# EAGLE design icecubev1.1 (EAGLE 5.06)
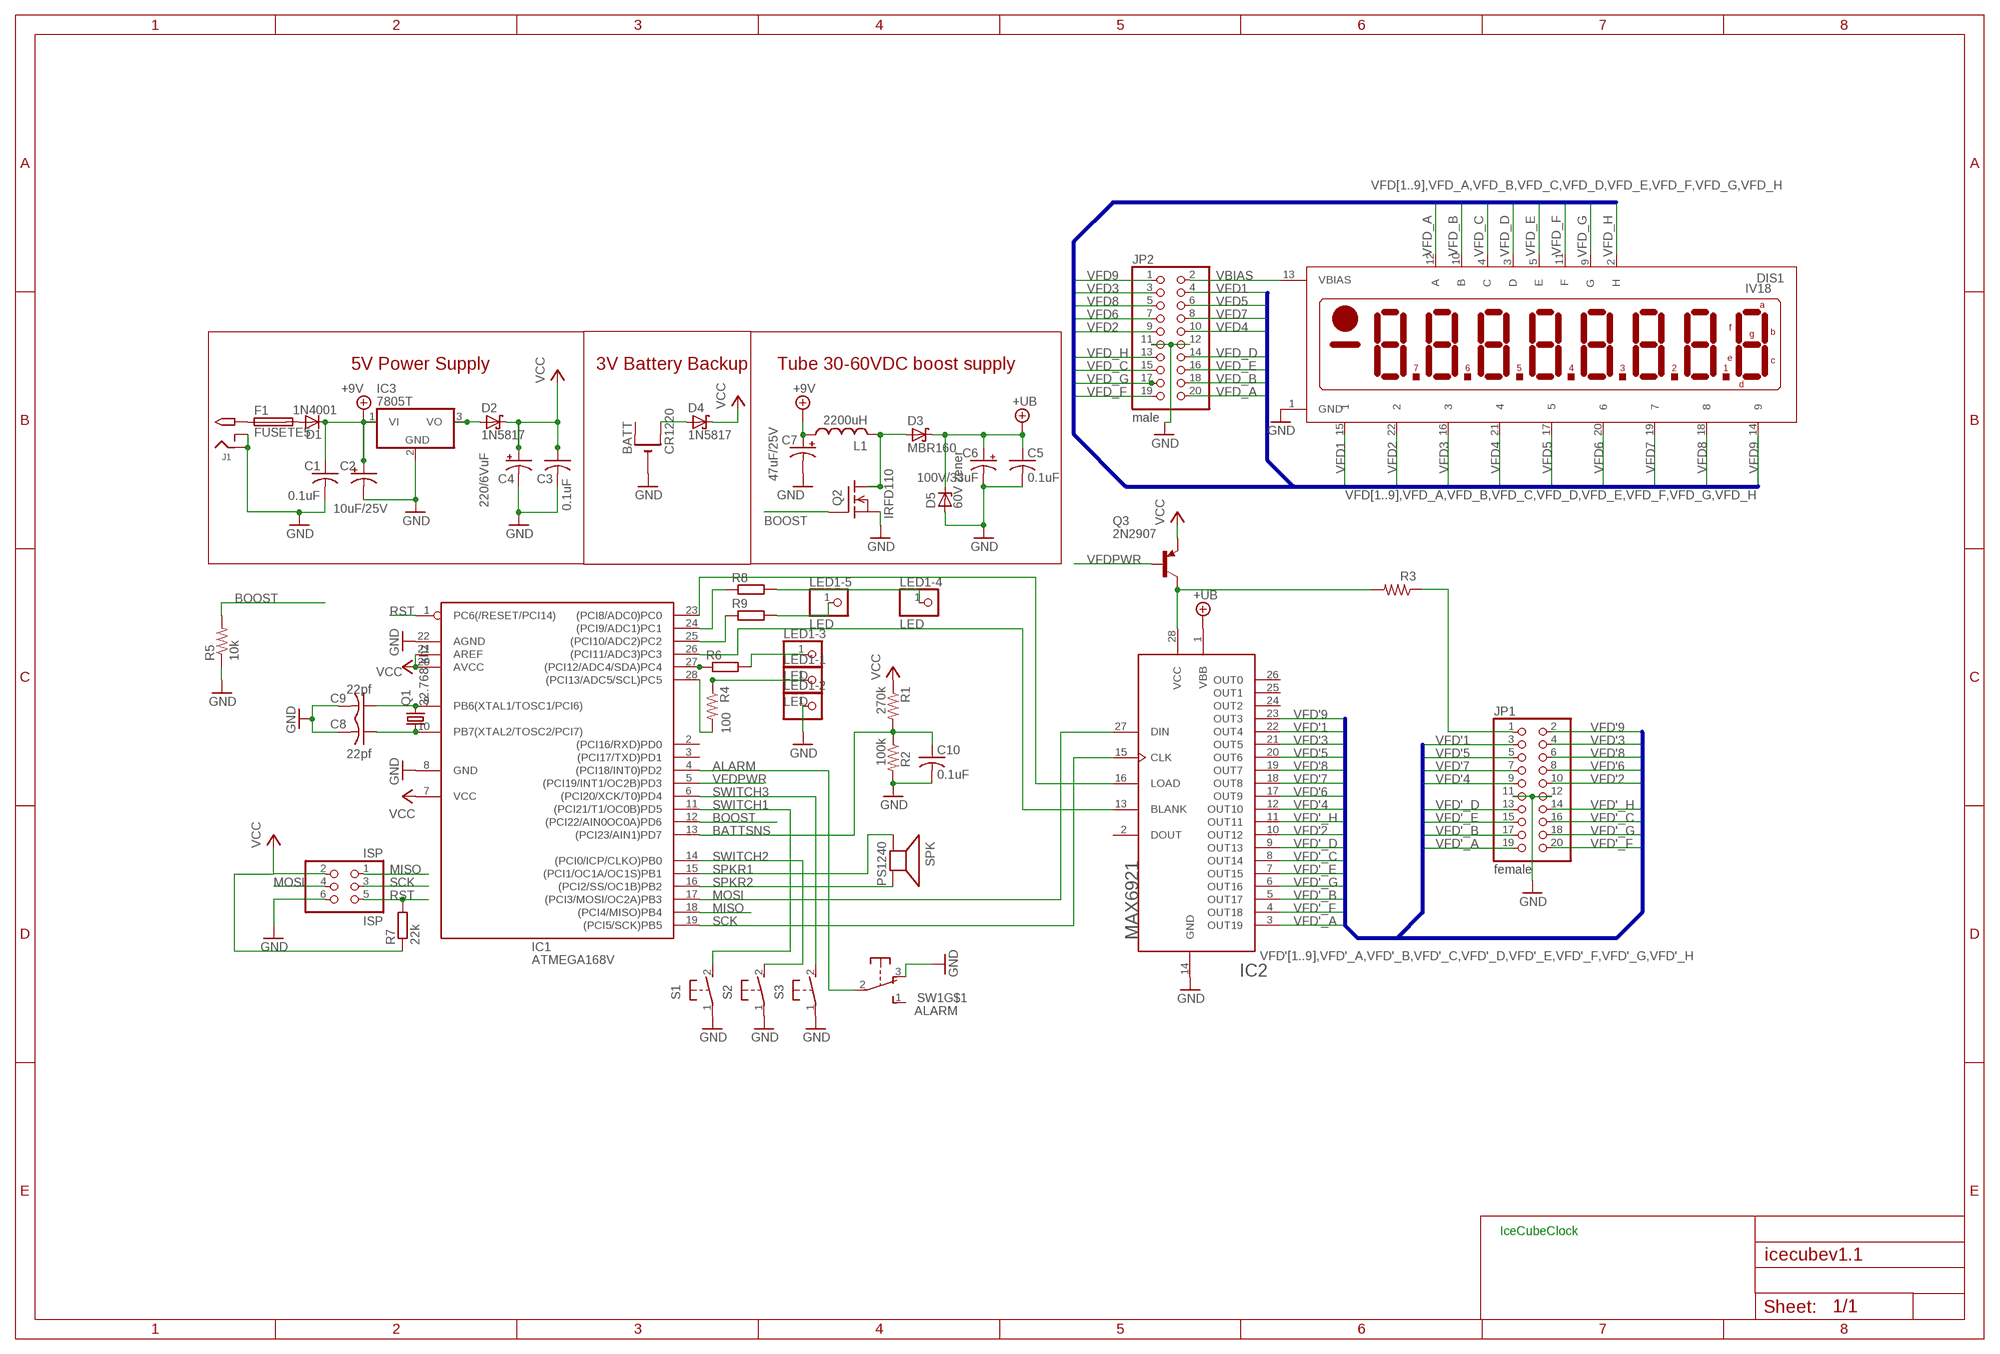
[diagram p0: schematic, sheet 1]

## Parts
BATT  CR1220  CR1220THM  [CR1220-THM]
C1  0.1uF  C-US025-025X050  [C025-025X050]
C2  10uF/25V  CPOL-USE2.5-6  [E2,5-6]
C3  0.1uF  C-US025-025X050  [C025-025X050]
C4  220/6VuF  CPOL-USE2.5-6  [E2,5-6]
C5  0.1uF  C-US025-024X044  [C025-024X044]
C6  100V/33uF  CPOL-USE3.5-8  [E3,5-8]
C7  47uF/25V  CPOL-USE2.5-6  [E2,5-6]
C8  22pf  C-US025-025X050  [C025-025X050]
C9  22pf  C-US025-025X050  [C025-025X050]
C10  0.1uF  C-US025-024X044  [C025-024X044]
D1  1N4001  1N4004  [DO41-10]
D2  1N5817  SCHOTTKY-DIODEDO41  [DO41-10]
D3  MBR160  SCHOTTKY-DIODEDO41  [DO41-10]
D4  1N5817  SCHOTTKY-DIODEDO41  [DO41-10]
D5  60V zener  ZENER-DIODEDO41Z10  [DO41Z10]
DIS1  IV18  [IV18]
F1  FUSETE5  [TE5]
IC1  ATMEGA168V  ATMEGA168PROUND  [DIL28/3]
IC2  MAX6921  [PLCC-S28]
IC3  7805T  [TO220H]
ISP  ISP  PINHD-2X3  [2X03]
J1  2.1MMJACK  [PJ-102A]
JP1  female  PINHD-2X10  [2X10]
JP2  male  PINHD-2X10  [2X10]
L1  2200uH  L  [6000]
LED1-1  LED  PINHD-1X1  [1X01]
LED1-2  PINHD-1X1  [1X01]
LED1-3  LED  PINHD-1X1  [1X01]
LED1-4  LED  PINHD-1X1  [1X01]
LED1-5  LED  PINHD-1X1  [1X01]
Q1  32.768 khz  CRYTALTC26V  [TC26V]
Q2  IRFD110  [DIL04]
Q3  2N2907  BC327-16-PNP-TO92-EBC  [TO92-EBC]
R1  270k  R-US_0207/10  [0207/10]
R2  100k  R-US_0207/10  [0207/10]
R3  22  R-US_0207/10  [0207/10]
R4  100  R-US_0207/5V  [0207/5V]
R5  10k  R-US_0207/5V  [0207/5V]
R6  R-EU_0204/5  [0204/5]
R7  22k  R-EU_0204/2V  [0204V]
R8  R-EU_0204/5  [0204/5]
R9  R-EU_0204/5  [0204/5]
S1  31-XX  [B3F-31XX]
S2  31-XX  [B3F-31XX]
S3  31-XX  [B3F-31XX]
SPK  PS1240  SPEAKER/PS12  [PS12]
SW1  ALARM  OS102011MA1Q  [OS102011MA1Q]

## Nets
+9V: C1.1 C2.+ C7.+ D1.C IC3.1(VI) L1.1
+UB: C5.1 C6.+ D3.C D5.C IC2.1(VBB)
ALARM: IC1.4((PCI18/INT0)PD2) SW1.2(P)
BATTSNS: C10.1 IC1.13((PCI23/AIN1)PD7) R1.2 R2.1
BLANK: IC1.26((PCI11/ADC3)PC3) IC2.13(BLANK)
BOOST: IC1.12((PCI22/AIN0OC0A)PD6) Q2.3(G) R5.2
GND: BATT.- C1.2 C2.- C3.2 C4.- C5.2 C6.- C7.- C8.2 C9.2 C10.2 D5.A DIS1.1(GND) IC1.8(GND) IC1.22(AGND) IC2.14(GND) IC3.2(GND) ISP.6 J1.RING J1.RING_SW JP1.11 JP1.12 JP2.11 JP2.12 LED1-2.1 Q2.4(S) R2.2 R5.1 S1.1(P) S2.1(P) S3.1(P) SW1.3(O)
LOAD: IC1.23((PCI8/ADC0)PC0) IC2.16(LOAD)
MISO: IC1.18((PCI4/MISO)PB4) ISP.1
MOSI: IC1.17((PCI3/MOSI/OC2A)PB3) IC2.27(DIN) ISP.4
N$1: C9.1 IC1.9(PB6(XTAL1/TOSC1/PCI6)) Q1.2
N$2: D3.A L1.2 Q2.1(D) Q2.2(D1)
N$3: C8.1 IC1.10(PB7(XTAL2/TOSC2/PCI7)) Q1.1
N$4: F1.1 J1.TIP
N$5: D1.A F1.2
N$6: IC1.27((PCI12/ADC4/SDA)PC4) R6.1
N$7: LED1-3.1 R6.2
N$8: IC1.24((PCI9/ADC1)PC1) R8.1
N$9: IC1.25((PCI10/ADC2)PC2) R9.1
N$10: BATT.+2(+1) D4.A
N$11: IC1.28((PCI13/ADC5/SCL)PC5) R4.2
N$12: LED1-5.1 R9.2
N$13: LED1-4.1 R8.2
N$34: JP1.1 R3.1
N$39: IC2.28(VCC) Q3.C R3.2
N$52: LED1-1.1 R4.1
N$53: D2.A IC3.3(VO)
RST: IC1.1(PC6(/RESET/PCI14)) ISP.5 R7.2
SCK: IC1.19((PCI5/SCK)PB5) IC2.15(CLK) ISP.3
SPKR1: IC1.15((PCI1/OC1A/OC1S)PB1) SPK.P$1(+)
SPKR2: IC1.16((PCI2/SS/OC1B)PB2) SPK.P$2(-)
SWITCH1: IC1.11((PCI21/T1/OC0B)PD5) S1.2(S)
SWITCH2: IC1.14((PCI0/ICP/CLKO)PB0) S2.2(S)
SWITCH3: IC1.6((PCI20/XCK/T0)PD4) S3.2(S)
VBIAS: DIS1.13(VBIAS) JP2.2
VCC: C3.1 C4.+ D2.C D4.C IC1.7(VCC) IC1.20(AVCC) IC1.21(AREF) ISP.2 Q3.E R1.1 R7.1
VFD1: DIS1.15 JP2.4
VFD2: DIS1.22 JP2.9
VFD3: DIS1.16 JP2.3
VFD4: DIS1.21 JP2.10
VFD5: DIS1.17 JP2.6
VFD6: DIS1.20 JP2.7
VFD7: DIS1.19 JP2.8
VFD8: DIS1.18 JP2.5
VFD9: DIS1.14 JP2.1
VFD'1: IC2.22(OUT4) JP1.3
VFD'2: IC2.10(OUT12) JP1.10
VFD'3: IC2.21(OUT5) JP1.4
VFD'4: IC2.12(OUT10) JP1.9
VFD'5: IC2.20(OUT6) JP1.5
VFD'6: IC2.17(OUT9) JP1.8
VFD'7: IC2.18(OUT8) JP1.7
VFD'8: IC2.19(OUT7) JP1.6
VFD'9: IC2.23(OUT3) JP1.2
VFD'_A: IC2.3(OUT19) JP1.19
VFD'_B: IC2.5(OUT17) JP1.17
VFD'_C: IC2.8(OUT14) JP1.16
VFD'_D: IC2.9(OUT13) JP1.13
VFD'_E: IC2.7(OUT15) JP1.15
VFD'_F: IC2.4(OUT18) JP1.20
VFD'_G: IC2.6(OUT16) JP1.18
VFD'_H: IC2.11(OUT11) JP1.14
VFD_A: DIS1.12(A) JP2.20
VFD_B: DIS1.10(B) JP2.18
VFD_C: DIS1.4(C) JP2.15
VFD_D: DIS1.3(D) JP2.14
VFD_E: DIS1.5(E) JP2.16
VFD_F: DIS1.11(F) JP2.19
VFD_G: DIS1.9(G) JP2.17
VFD_H: DIS1.2(H) JP2.13
VFDPWR: IC1.5((PCI19/INT1/OC2B)PD3) Q3.B
Unconnected: BATT.+1(+) IC1.2((PCI16/RXD)PD0) IC1.3((PCI17/TXD)PD1) IC2.2(DOUT) IC2.24(OUT2) IC2.25(OUT1) IC2.26(OUT0) SW1.1(S) SW1.MT1(MT) SW1.MT2(MT)

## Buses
VFD[1..9],VFD_A,VFD_B,VFD_C,VFD_D,VFD_E,VFD_F,VFD_G,VFD_H
VFD'[1..9],VFD'_A,VFD'_B,VFD'_C,VFD'_D,VFD'_E,VFD'_F,VFD'_G,VFD'_H

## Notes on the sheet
- 5V Power Supply | 3V Battery Backup | Tube 30-60VDC boost supply
- IceCubeClock

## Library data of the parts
BATT = vfd:CR1220
C1 C3 C8 C9 = minimidi:C-US: CAPACITOR, American symbol
C2 C4 C7 = minimidi:CPOL-US: POLARIZED CAPACITOR, American symbol
C5 C10 = rcl-ez:C-US: CAPACITOR, American symbol
C6 = rcl-ez:CPOL-US: POLARIZED CAPACITOR, American symbol
D1 = minimidi:1N4004: DIODE
D2-D4 = usbbuck:SCHOTTKY-DIODE: Schottky Diode
D5 = diode:ZENER-DIODE: Z-Diode
DIS1 = vfd:IV18: LCD DISPLAY 8-character 7 segment
F1 = fuse:FUSE: Fuse
IC1 = avr:ATMEGA168*P: MICROCONTROLLER 16 kBytes FLASH 1 kBytes SRAM 512 Bytes EEPROM USART 8-channel 10 bit ADC
IC2 = vfd:MAX6921
IC3 = linear:78*: Positive VOLTAGE REGULATOR
ISP = pinhead-ez:PINHD-2X3: PIN HEADER
J1 = minimidi:2.1MMJACK
JP1 JP2 = pinhead:PINHD-2X10: PIN HEADER
L1 = usbbuck:L
LED1-1-LED1-5 = ybox2:PINHD-1X1: PIN HEADER
Q1 = crystal:CRYTAL: CRYSTAL
Q2 = vfd:IRFD110
Q3 = transistor:*-PNP-: PNP Transistror
R1-R5 = minimidi:R-US_: RESISTOR, American symbol
R6 R8 R9 = resistor:R-EU_: RESISTOR, European symbol
R7 = rcl:R-EU_: RESISTOR, European symbol
S1-S3 = switch-omron:31-XX: OMRON SWITCH
SPK = ybox2:SPEAKER: SPEAKER
SW1 = adaprog:OS102011MA1Q

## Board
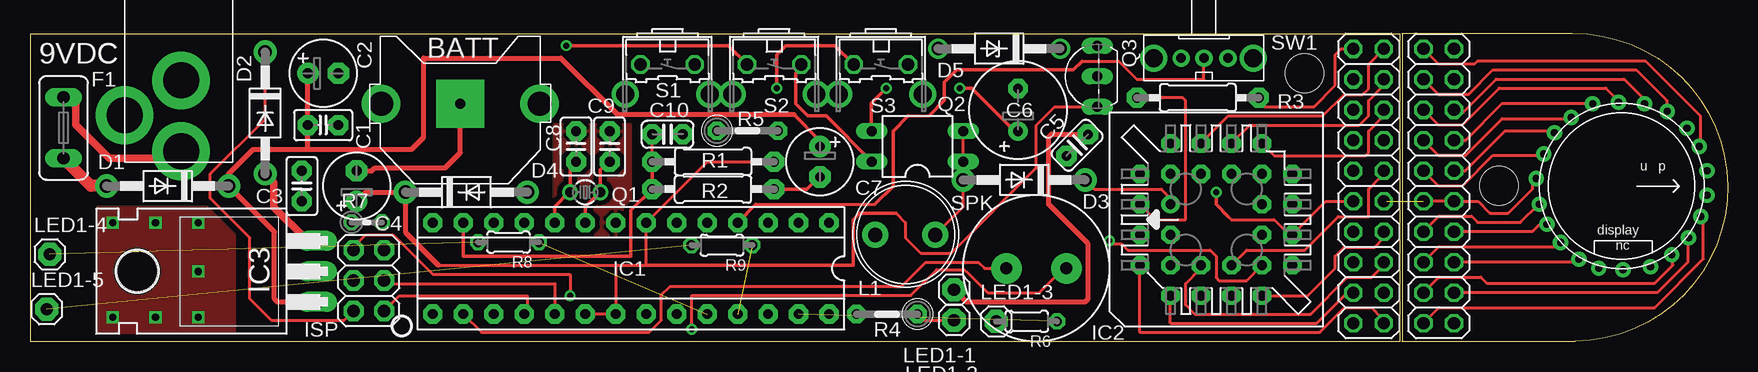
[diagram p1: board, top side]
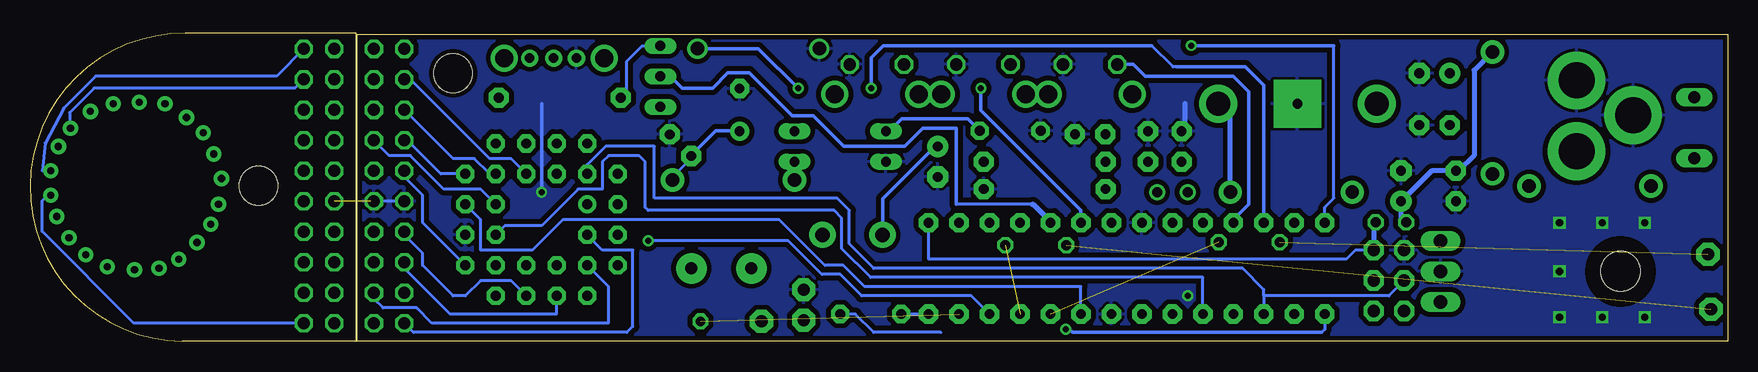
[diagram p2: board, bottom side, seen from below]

Size 141.47 x 25.68 mm. Coordinates in mm from the lower left corner, seen from the top.
Outline: 114.34,25.65 114.34,0
Outline: 114.3,0.03 128.77,0.03 arc180 128.52,25.68 114.3,25.68
Outline: 0,0.04 114.2,0.04 114.2,25.62 0,25.62 0,0.04
Copper layers (1*16): Top 0.035mm / dielectric 1.5mm / Bottom 0.035mm
Design rules "default *": minimum track width 10mil, minimum drill 19mil, track to track 12mil, track to pad 12mil, pad to pad 20mil, via to via 12mil, smd to smd 0mil, copper to edge 12mil, drill to drill 8mil, minimum pad ring 10mil, minimum via ring 8mil, stop-mask expansion 4mil, vias tented up to drill 20mil, thermal gap 10mil
Holes 3.2 mm at 106.21,22.35 122.42,12.98

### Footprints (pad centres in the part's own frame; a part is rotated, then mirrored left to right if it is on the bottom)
CR1220-THM = drill 2 pad 3.175 round: +1 -6.604,0; +2 6.604,0 | drill 0.8 pad 3.962 square: - 0,0
C025-025X050 = drill 0.813 pad 1.676 octagon: 1 -1.27,0; 2 1.27,0
E2,5-6 = drill 0.813 pad 1.778 round: + -1.27,0 | drill 0.813 pad 1.778 octagon: - 1.27,0
C025-024X044 = drill 0.813 pad 1.676 octagon: 1 -1.27,0; 2 1.27,0
E3,5-8 = drill 0.813 pad 1.6 round: + -1.778,0 | drill 0.813 pad 1.6 octagon: - 1.778,0
DO41-10 = drill 1.118 pad 1.93 round: A 5.08,0; C -5.08,0
DO41Z10 = drill 1.118 round: A 5.08,0; C -5.08,0
IV18 = drill 0.6 pad 1.27 round: 1 -0.635,-7.112; 2 1.524,-6.858; 3 3.175,-6.223; 4 4.699,-5.08; 5 6.096,-3.556; 6 6.858,-1.905; 7 6.985,0.127; 8 6.731,2.413; 9 5.715,4.191; 10 4.318,5.588; 11 2.54,6.604; 12 0.762,7.112; 13 -1.27,7.112; 14 -3.302,6.477; 15 -4.826,5.461; 16 -6.223,3.81; 17 -6.858,1.905; 18 -6.985,-0.254; 19 -6.858,-2.413; 20 -5.715,-4.191; 21 -4.445,-5.588; 22 -2.667,-6.477
TE5 = drill 1.016 long: 1 -2.54,0; 2 2.54,0
DIL28/3 = drill 0.813 pad 1.6 octagon: 1 -16.51,-3.81; 2 -13.97,-3.81; 3 -11.43,-3.81; 4 -8.89,-3.81; 5 -6.35,-3.81; 6 -3.81,-3.81; 7 -1.27,-3.81; 8 1.27,-3.81; 9 3.81,-3.81; 10 6.35,-3.81; 11 8.89,-3.81; 12 11.43,-3.81; 13 13.97,-3.81; 14 16.51,-3.81; 15 16.51,3.81; 16 13.97,3.81; 17 11.43,3.81; 18 8.89,3.81; 19 6.35,3.81; 20 3.81,3.81; 21 1.27,3.81; 22 -1.27,3.81; 23 -3.81,3.81; 24 -6.35,3.81; 25 -8.89,3.81; 26 -11.43,3.81; 27 -13.97,3.81; 28 -16.51,3.81
PLCC-S28 = drill 0.813 pad 1.524 round: 1 1.27,3.81 | drill 0.813 pad 1.524 octagon: 2 -1.27,6.35; 3 -1.27,3.81; 4 -3.81,6.35; 5 -6.35,3.81; 6 -3.81,3.81; 7 -6.35,1.27; 8 -3.81,1.27; 9 -6.35,-1.27; 10 -3.81,-1.27; 11 -6.35,-3.81; 12 -3.81,-6.35; 13 -3.81,-3.81; 14 -1.27,-6.35; 15 -1.27,-3.81; 16 1.27,-6.35; 17 1.27,-3.81; 18 3.81,-6.35; 19 6.35,-3.81; 20 3.81,-3.81; 21 6.35,-1.27; 22 3.81,-1.27; 23 6.35,1.27; 24 3.81,1.27; 25 6.35,3.81; 26 3.81,6.35; 27 3.81,3.81; 28 1.27,6.35
TO220H = drill 1.118 long: 1 -2.54,-10.16; 2 0,-10.16; 3 2.54,-10.16 | hole 3.302: 0,4.826
2X03 = drill 1.016 pad 1.676 octagon: 1 -2.54,-1.27; 2 -2.54,1.27; 3 0,-1.27; 4 0,1.27; 5 2.54,-1.27; 6 2.54,1.27
PJ-102A = drill 3 pad 4.8 round: RING 0.1,-3.39; RING_SW -4.6,-6.29; TIP 0.1,-9.29
2X10 = drill 1.016 octagon: 1 -11.43,-1.27; 2 -11.43,1.27; 3 -8.89,-1.27; 4 -8.89,1.27; 5 -6.35,-1.27; 6 -6.35,1.27; 7 -3.81,-1.27; 8 -3.81,1.27; 9 -1.27,-1.27; 10 -1.27,1.27; 11 1.27,-1.27; 12 1.27,1.27; 13 3.81,-1.27; 14 3.81,1.27; 15 6.35,-1.27; 16 6.35,1.27; 17 8.89,-1.27; 18 8.89,1.27; 19 11.43,-1.27; 20 11.43,1.27
6000 = drill 1.2 pad 2.184 round: 1 -2.5,0; 2 2.5,0
1X01 = drill 1.016 pad 1.93 octagon: 1 0,0
TC26V = drill 0.813 round: 1 -1.27,0; 2 1.27,0
DIL04 = drill 0.813 long: 1 -1.27,-3.81; 2 1.27,-3.81; 3 1.27,3.81; 4 -1.27,3.81
TO92-EBC = drill 0.813 long: B 0,-1.27; C 2.54,-1.27; E -2.54,-1.27
0207/10 = drill 0.813 pad 1.676 octagon: 1 -5.08,0; 2 5.08,0
0207/5V = drill 0.813 pad 1.524 octagon: 1 -2.54,0; 2 2.54,0
0204/5 = drill 0.813 octagon: 1 -2.54,0; 2 2.54,0
0204V = drill 0.813 octagon: 1 -1.27,0; 2 1.27,0
B3F-31XX = drill 1.016 octagon: 1 -2.261,-1.245; 2 2.261,-1.245 | drill 1.499 pad 2.159 round: 3 -3.505,1.245; 4 3.505,1.245
PS12 = drill 1 pad 2.54 round: P$1 -2.5,0; P$2 2.5,0
OS102011MA1Q = drill 0.8 pad 1.422 round: 1 -2,0; 2 0,0; 3 1.9,0 | drill 1.5 pad 2.184 round: MT1 -4.1,0; MT2 4.2,0

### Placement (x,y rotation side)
BATT  35.86,19.81 0 top
C1  24.43,18.03 0 top
C2  24.43,22.35 0 top
C3  22.65,12.95 270 top
C4  27.22,12.95 90 top
C5  87.27,16.36 45 top
C6  82.34,19.3 90 top
C7  65.83,14.99 270 top
C8  45.51,16.26 90 top
C9  48.3,16.26 90 top
C10  53.13,17.27 0 top
D1  11.47,12.95 180 top
D2  19.6,19.05 270 top
D3  82.85,13.46 180 top
D4  36.36,12.45 0 top
D5  80.77,24.41 180 top
DIS1  132.63,12.95 270 top
F1  2.79,17.81 270 top
IC1  50.08,6.1 180 top
IC2  98.85,10.16 90 top
IC3  13.76,5.84 90 top
ISP  28.24,5.08 90 top
J1  12.49,25.15 0 top
JP1  111.55,12.95 270 top
JP2  117.39,12.95 270 top
L1  72.94,8.89 0 top
LED1-1  77,1.78 0 top
LED1-2  77,4.32 0 top
LED1-3  80.51,1.68 0 top
LED1-4  1.65,7.26 0 top
LED1-5  1.39,2.69 0 top
Q1  46.27,12.45 0 top
Q2  73.96,16.26 90 top
Q3  87.67,22.1 90 top
R1  56.92,14.99 180 top
R2  56.92,12.7 0 top
R3  97.32,20.32 180 top
R4  71.42,2.29 180 top
R5  59.79,17.56 0 top
R6  83.05,1.68 180 top
R7  28.06,9.93 0 top
R8  39.87,8.28 180 top
R9  57.65,8.03 180 top
S1  53.13,21.84 180 top
S2  62.02,21.84 180 top
S3  70.91,21.84 180 top
SPK  83.86,6.1 180 top
SW1  97.83,23.62 180 top

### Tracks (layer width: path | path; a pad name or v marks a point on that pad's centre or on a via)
+9V
  Top 0.305: 63.65,18.92 65.78,16.79
  Top 0.406: C2.+ C1.1 23.16,16 | 23.16,16 31.79,16 32.81,17.02 32.81,23.62 44.24,23.62 48.94,18.92 63.65,18.92 | IC3.1 20.62,3.3 20.36,3.56 20.36,9.14 D1.C 16.55,13.97 18.58,16 23.16,16 | C7.+ 65.81,16.26 65.78,16.28 65.78,16.79
  Bottom 0.254: 70.4,8.89 L1.1
  Bottom 0.305: C7.+ 66.01,16.26 66.04,16.28 70.4,11.92 70.4,8.89
+UB  (via drill 0.5)
  Top 0.254: D3.C 88.69,12.7 94.28,12.7 95.04,11.94 IC2.1
  Top 0.305: C6.+ 82.34,17.34 82.29,17.3 78.48,21.11 v77.47,21.11
  Bottom 0.254: 87.93,13.21 D3.C 87.93,13.72 | 87.93,13.72 87.93,13.91 | 86.4,15.49 C5.1 86.37,15.27 87.93,13.72
  Bottom 0.305: C6.+ 82.36,17.55 84.34,17.55 86.4,15.49 | D5.C 80.77,24.41 v77.47,21.11
ALARM
  Top 0.254: 60.49,11.43 70.4,11.43 | 87.67,23.37 90.72,23.37 92.24,21.84 97.83,21.84 SW1.2 | 73.19,18.8 74.9,18.8 74.93,18.82
  Top 0.305: 73.19,18.8 71.92,17.53 71.92,12.95 70.4,11.43 | IC1.4 60.49,11.43 | 87.67,23.37 86.94,22.63 77.21,22.63 76.2,21.62 76.2,20.09 74.93,18.82
BATTSNS
  Top 0.254: C10.1 51.86,14.99 R1.2
  Top 0.305: IC1.13 36.11,7.11 50.08,7.11 50.08,10.92 51.86,12.7 R2.1 | R2.1 51.84,12.46 | R2.1 R1.2
BLANK  (via drill 0.5)
  Top 0.254: IC2.13 101.39,5.08 99.1,5.08 98.85,5.33 98.85,7.11 98.34,7.62 91.48,7.62 90.97,8.13 89.96,8.13 v89.96,8.38
  Bottom 0.254: IC1.26 63.03,3.81 72.18,3.81 73.96,5.59 75.48,5.59 78.27,8.38 v89.96,8.38
BOOST  (via drill 0.5)
  Top 0.305: Q2.3 70.1,17.48 70.1,17.3 70.1,19.84 v71.37,21.11
  Top 0.406: Q2.3 70.1,17.53 70.1,17.3
  Bottom 0.254: 45.97,22.89 46.22,22.89 48,24.66
  Bottom 0.305: IC1.12 38.65,21.34 40.2,22.89 45.97,22.89 | 48,24.66 70.35,24.66 71.37,23.65 v71.37,21.11 | R5.2 63.34,18.57 68.83,18.57 69.84,17.55 70.12,17.55 Q2.3
GND  (via drill 0.5, 0.6)  (1 unrouted)
  Top 0.254: IC1.22 51.35,2.03 | 64.3,23.09 S2.1 64.25,23.11 | v45,3.81 45,5.59 33.57,5.59 30.27,8.89 27.98,8.89 26.97,7.87 ISP.6 | JP1.11 107.99,11.68 IC2.14 104.94,8.89 103.67,10.16 100.12,10.16 99.86,10.41 | 118.69,11.71 118.87,11.71 | 118.69,11.71 JP2.12 120.67,11.68 121.66,10.69 123.19,10.69 125.22,12.73 125.22,13.23 125.52,13.53 DIS1.1 | JP2.11 116.15,11.71 118.69,11.71
  Top 0.305: 64.25,23.11 64.05,23.11 64.05,22.61 63.8,22.35 63.8,19.81 64.81,18.8 66.34,18.8 Q2.4 | 99.86,10.41 98.85,11.43 v98.85,12.45 | C7.- 65.81,13.72 65.78,13.74 64.74,12.7 R2.2
  Top 0.406: LED1-2.1 78.02,3.3 87.93,3.3 88.18,3.56 88.18,8.13 84.88,11.43 84.88,17.02 85.13,17.27 88.18,17.27 | 88.18,17.27 88.43,17.27 | 88.18,17.27 C5.2 | C4.- 28.49,14.22 28.74,14.48 34.59,14.48 35.86,15.75 BATT.-
  Bottom 0.254: 113.07,11.68 JP1.12 JP1.11
  Bottom 0.305: v98.85,12.45 98.85,19.81
  Bottom 0.406: C8.2 45.21,17.53 45.21,19.84
  other vias: 6.9,9.91 10.46,9.91 14.01,9.91 14.01,5.84 14.01,2.03 10.46,2.03 6.9,2.03
  pour Bottom (isolate 0.406): -0.62,25.65 -0.62,0 113.83,0.25 114.09,25.91
  pour Top: 5.63,11.18 5.63,0.76 17.06,0.76 17.06,8.89 14.77,11.18
  pour Top (isolate 0.406): 43.68,18.06 43.68,8.92 50.03,8.92 50.03,18.06
LOAD
  Bottom 0.254: 105.45,11.68 IC2.16 103.93,10.16 103.93,7.62 99.61,7.62 97.07,10.16 79.04,10.16 75.23,6.35 73.7,6.35 71.92,4.57 53.89,4.57 IC1.23
MISO
  Top 0.254: IC1.18 41.44,2.29 41.44,3.81 30.78,3.81 ISP.1
MOSI
  Bottom 0.254: 38.65,3.81 IC1.17 | 38.65,3.81 38.65,4.32 40.43,6.1 71.16,6.1 73.19,8.13 73.19,10.92 74.21,11.94 89.45,11.94 89.45,16.26 93.51,16.26 95.04,14.73 IC2.27 | ISP.4 28.24,3.81 38.65,3.81
N$1
  Top 0.305: IC1.9 46.27,11.25 47.47,12.45 Q1.2 47.54,14.3 48.25,15.01 48.28,14.99 C9.1
N$2
  Top 0.254: L1.2 77.77,11.22 D3.A | Q2.1 Q2.2
  Bottom 0.254: D3.A Q2.1
N$3
  Top 0.305: C8.1 45.49,14.99 45.46,15.01 45,14.55 Q1.1 44.98,12.45 44.95,12.47 43.73,11.25 IC1.10
N$4
  Top 0.61: J1.TIP 12,15.27 6.6,15.27 3.81,18.06 3.81,20.09 3.3,20.6 2.79,20.6 F1.1
N$5
  Top 1.016: D1.A 6.37,12.98 5.08,12.98 F1.2
N$6  (1 unrouted)
N$7  (1 unrouted)
N$8  (1 unrouted)
N$9  (1 unrouted)
N$10
  Bottom 0.406: BATT.+2 41.44,19.81 D4.A
N$11
  Bottom 0.254: IC1.28 R4.2
N$12  (1 unrouted)
N$13  (1 unrouted)
N$34
  Top 0.254: JP1.1 109.26,24.38 108.75,23.88 108.75,21.34 107,19.58 102.87,19.58 102.36,20.09 102.36,20.35 102.38,20.35 R3.1
N$39
  Top 0.254: IC2.28 93.77,10.16 96.31,10.16 96.31,20.07 96.05,20.32 R3.2
  Bottom 0.254: 92.12,20.19 R3.2 91.74,20.83 91.74,23.37 90.47,24.64 Q3.C
N$52
  Top 0.254: R4.1 73.96,1.78 LED1-1.1
  Bottom 0.254: 65.57,0.76 71.16,0.76 72.69,2.29 R4.1
N$53
  Top 0.61: IC3.3 23.13,8.38 20.32,11.2 20.32,13.23 19.6,13.95 D2.A
RST
  Bottom 0.254: 66.59,9.65 66.59,9.4 | 66.59,9.65 IC1.1 | 66.59,9.65 66.59,6.86 31.79,6.86 31.03,7.62 ISP.5
  Bottom 0.406: R7.2 29.51,10.31 ISP.5
SCK
  Top 0.254: IC1.19 43.73,4.83 29.76,4.83 ISP.3
  Bottom 0.254: IC1.19 43.73,5.33 71.42,5.33 73.83,7.75 73.83,10.29 74.46,10.92 89.96,10.92 90.21,11.18 90.21,14.99 90.72,15.49 93.26,15.49 93.77,14.99 93.77,12.7 95.8,12.7 98.85,9.65 101.9,9.65 IC2.15
SPKR1  (via drill 0.5)
  Top 0.254: 86.4,6.1 SPK.P$1 86.15,6.1 84.12,4.06 79.8,4.06 78.02,5.84 78,5.84 77.85,5.99 75.56,5.99 73.4,3.84 55.16,3.84 v55.16,1.02
  Bottom 0.254: 33.82,0.76 33.57,1.02 IC1.15 | 54.6,0.79 54.83,1.02 v55.16,1.02
  Bottom 0.305: v55.16,1.02 54.88,1.02 54.86,1.04 54.58,0.76 33.82,0.76
SPKR2
  Top 0.254: IC1.16 37.63,0.76 51.6,0.76 52.62,1.78 52.62,3.81 52.6,3.81 52.57,3.84 53.34,4.6 72.64,4.6 74.65,6.6 79.04,6.6 79.54,6.1 SPK.P$2
SWITCH1
  Bottom 0.305: 41.19,10.16 39.92,11.43 39.92,20.83 41.19,22.1 48.56,22.1 49.55,23.09 S1.2 | IC1.11 41.19,10.16 | 41.19,10.16 41.44,9.91
SWITCH2  (via drill 0.5)
  Top 0.305: S2.2 58.18,24.66 v44.7,24.66
  Bottom 0.254: IC1.14 33.57,11.18 32.81,11.94 32.81,24.64
  Bottom 0.305: 32.81,24.64 32.83,24.66 v44.7,24.66
SWITCH3  (via drill 0.5)
  Top 0.305: S3.2 67.07,24.66 62.99,24.66 62.22,23.9 v62.22,21.11
  Bottom 0.305: IC1.6 53.89,10.92 54.4,11.43 62.01,19.04 62.22,19.26 v62.22,21.11 62.48,21.11
VBIAS
  Bottom 0.254: JP2.2 120.92,22.12 136.01,22.12 138.68,19.46 140.2,16.54 140.46,14.25 139.77,14.25 DIS1.13
VCC
  Top 0.254: IC1.20 IC1.21 48.81,6.35 | 48.81,6.35 51.35,6.35 IC1.7 56.43,14.99 R1.1 | 34.08,6.35 48.81,6.35 | 72.18,10.67 72.94,9.91 72.94,8.64 74.21,7.37 76.75,7.37 83.86,14.48 83.86,18.03 85.39,19.56 Q3.E | ISP.2 26.2,1.78 20.11,1.78 18.33,3.56 18.33,8.64 15.03,11.94 15.03,13.97 19.6,18.54 D2.C
  Top 0.305: 72.18,10.67 69.13,10.67 68.62,10.16 68.62,6.35 51.35,6.35 | 34.08,6.35 34.06,6.35 34.03,6.38
  Top 0.406: 34.03,6.38 31.28,9.12 D4.C 27.98,12.45 C4.+
  Bottom 0.254: IC1.7 51.1,9.91 51.1,10.16
  Bottom 0.406: D2.C 21.12,22.61 21.12,15.49 22.39,14.22 C3.1 24.68,14.22 C4.+ 27.22,10.06 26.92,10.06 26.92,9.93 R7.1
VFD1
  Bottom 0.254: JP2.4 119.4,21.11 136.14,21.11 138.17,19.08 138.17,17.86 DIS1.15
VFD2
  Top 0.254: JP2.9 117.37,12.98 119.38,12.98 121.92,15.52 126.23,15.52 126.23,15.54 DIS1.22
VFD3
  Top 0.254: JP2.3 117.37,20.6 119.88,20.6 121.92,22.63 133.85,22.63 136.39,20.09 136.39,19.33 136.44,19.28 DIS1.16
VFD4
  Top 0.254: JP2.10 119.6,14.22 122.93,17.55 127.19,17.55 | 127.19,17.55 127.25,17.55 | 127.19,17.55 DIS1.21
VFD5
  Top 0.254: DIS1.17 134.56,19.84 134.62,19.84 134.62,20.09 132.84,21.87 122.17,21.87 119.38,19.08 119.12,19.08 118.87,19.33 118.84,19.3 JP2.6
VFD6
  Top 0.254: JP2.7 117.37,15.52 119.63,15.52 122.68,18.57 128.52,18.57 128.52,18.59 DIS1.20
VFD7
  Top 0.254: DIS1.19 130.19,19.84 122.68,19.84 119.63,16.79 118.87,16.79 118.84,16.76 JP2.8
VFD8
  Top 0.254: JP2.5 117.37,18.06 119.38,18.06 122.42,21.11 131.31,21.11 132.33,20.09 132.33,19.89 | 132.33,19.89 132.33,19.84 | 132.33,19.89 DIS1.18
VFD9
  Top 0.254: JP2.1 117.37,23.14 120.39,23.14 120.65,23.39 134.62,23.39 139.19,18.82 139.19,16.28 139.13,16.28 DIS1.14
VFD'1
  Bottom 0.254: IC2.22 101.39,15.24 103.17,15.24 109.77,21.84 JP1.3
VFD'2
  Top 0.254: IC2.10 101.39,7.62 106.21,7.62 109.01,10.41 111.55,10.41 111.55,12.7 112.56,13.72 112.56,14.22 JP1.10
VFD'3
  Top 0.254: IC2.21 101.64,18.03 110.79,18.03 111.55,18.8 111.55,20.07 112.82,21.34 JP1.4
VFD'4
  Bottom 0.254: IC2.12 108.75,9.91 108.75,12.19 110.28,13.72 JP1.9
VFD'5
  Bottom 0.254: JP1.5 106.21,15.24 104.44,15.24 103.17,13.97 IC2.20
VFD'6
  Bottom 0.254: IC2.17 103.93,12.7 106.98,12.7 109.77,15.49 111.55,15.49 JP1.8 113.07,16.76
VFD'7
  Bottom 0.254: IC2.18 107.23,13.97 110.02,16.76 JP1.7
VFD'8
  Top 0.254: IC2.19 103.67,15.49 111.29,15.49 111.55,15.75 111.55,17.53 112.82,18.8 JP1.6
VFD'9
  Top 0.254: IC2.23 99.86,18.8 107.74,18.8 109.52,20.57 111.04,20.57 111.55,21.08 111.55,23.11 JP1.2
VFD'_A
  Bottom 0.254: JP1.19 109.52,0.76 91.74,0.76 91.23,1.27 91.23,7.62 93.77,7.62 IC2.3
VFD'_B
  Top 0.254: IC2.5 95.04,1.52 107.23,1.52 109.77,4.06 JP1.17
VFD'_C
  Top 0.254: IC2.8 97.58,6.1 96.31,4.83 96.31,3.05 97.07,2.29 106.72,2.29 109.77,5.33 111.8,5.33 112.82,6.35 JP1.16
VFD'_D
  Bottom 0.254: IC2.9 101.39,5.08 103.93,5.08 105.2,3.81 106.21,3.81 108.75,6.35 108.75,7.37 110.53,9.14 JP1.13
VFD'_E
  Bottom 0.254: IC2.7 97.58,2.29 106.47,2.29 110.28,6.1 JP1.15
VFD'_F
  Top 0.254: IC2.4 92.5,0.76 107.48,0.76 109.52,2.79 111.8,2.79 112.56,2.03 112.56,1.78 JP1.20
VFD'_G
  Bottom 0.254: IC2.6 93.26,4.57 93.26,1.52 107.99,1.52 109.26,2.79 112.06,2.79 112.82,3.56 JP1.18
VFD'_H
  Top 0.254: IC2.11 106.47,3.81 108.75,6.1 108.75,7.11 109.52,7.87 112.06,7.87 112.82,8.64 JP1.14
VFD_A
  Bottom 0.254: JP2.20 132.81,1.52 140.46,9.17 140.46,11.71 139.95,12.22 139.92,12.19 DIS1.12
VFD_B
  Top 0.254: JP2.18 118.69,4.09 135.63,4.09 138.17,6.63 138.17,8.66 138.19,8.66 DIS1.10
VFD_C
  Top 0.254: JP2.15 117.42,7.9 127.76,7.9 127.76,8.05 DIS1.4
VFD_D
  Top 0.254: JP2.14 118.69,9.17 125.22,9.17 125.73,9.68 126.31,9.68 DIS1.3
VFD_E
  Top 0.254: DIS1.5 128.84,6.63 118.69,6.63 JP2.16
VFD_F
  Top 0.254: JP2.19 117.42,2.82 135.38,2.82 139.44,6.88 139.44,10.21 DIS1.11
VFD_G
  Top 0.254: JP2.17 117.42,5.36 120.9,5.36 121.41,4.85 135.38,4.85 136.9,6.38 136.9,7.16 DIS1.9
VFD_H
  Top 0.254: JP2.13 117.42,10.44 120.14,10.44 120.65,9.93 124.2,9.93 125.73,11.46 125.75,11.46 DIS1.2
VFDPWR
  Bottom 0.254: 57.95,11.43 64.29,11.43
  Bottom 0.305: 64.29,11.43 64.29,17.78 67.08,17.78 68.58,16.28 73.66,16.28 76.2,18.82 77.97,18.82 81.53,22.38 83.31,22.38 84.58,21.11 87.12,21.11 88.26,22.25 | 88.26,22.25 88.64,21.87 89.4,21.87 89.15,22.12 88.92,22.12 | 88.26,22.25 88.13,22.38 | 88.92,22.12 88.9,22.12 | 88.92,22.12 Q3.B
  Bottom 0.406: IC1.5 56.41,9.91 56.38,9.93 57.88,11.43 57.95,11.43

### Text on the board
tPlace: 9VDC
